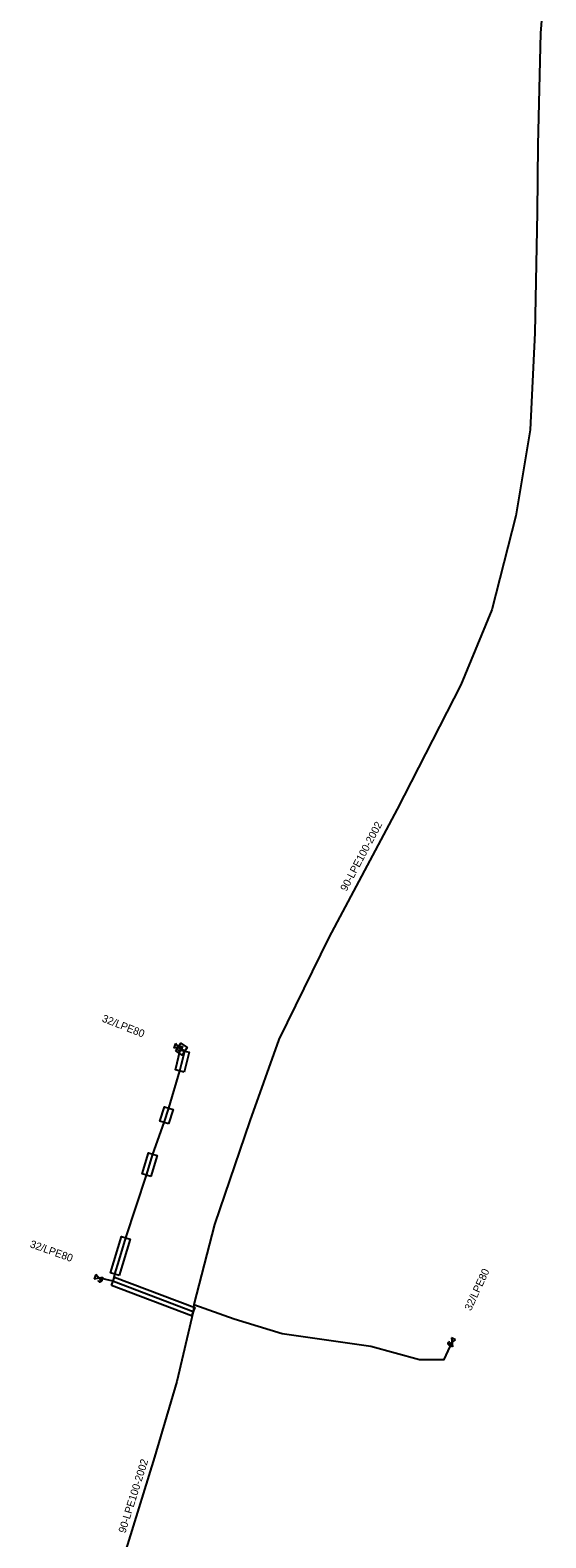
# Model space of a CAD drawing. Extents: x -787723 to -786204, y -1153846 to -1152384.
# Drawn here: x -787402.7 to -787334.7, y -1152971.6 to -1152772.9 of the extents above; entities that cross this region are included whole.
import ezdxf

# ---------------------------------------------------------------- set-up
doc = ezdxf.new("R2010")
doc.units = 0
for name, color, linetype in [('Vrstva 1', 7, 'Continuous'), ('Vrstva 21', 7, 'Continuous'), ('Vrstva 29', 7, 'Continuous'), ('Vrstva 31', 7, 'Continuous'), ('Vrstva 32', 7, 'Continuous')]:
    doc.layers.add(name, color=color, linetype=linetype)

# ---------------------------------------------------------------- blocks, each defined once
blk = doc.blocks.new('DEC063-SN')
at = {"layer": 'Vrstva 1'}
for p, q in [((-0.5, -0.3), (0.5, 0.3)), ((0.5, -0.3), (-0.5, 0.3)), ((-0.5, 0.3), (-0.5, -0.3)), ((0.5, 0.3), (0.5, -0.3)), ((0.126, -0.318), (0.126, -0.458)), ((0.126, -0.384), (0.206, -0.384)), ((0.206, -0.458), (0.206, -0.318)), ((0.366, -0.458), (0.366, -0.318))]:
    blk.add_line(p, q, dxfattribs=at)
for points in [[(0.246, -0.318), (0.246, -0.418), (0.252, -0.438), (0.264, -0.451), (0.281, -0.458), (0.292, -0.458), (0.309, -0.451), (0.321, -0.438), (0.326, -0.418), (0.326, -0.318)], [(0.366, -0.318), (0.418, -0.318), (0.435, -0.325), (0.441, -0.331), (0.446, -0.344), (0.446, -0.364), (0.441, -0.378), (0.435, -0.384), (0.418, -0.391), (0.366, -0.391)]]:
    blk.add_lwpolyline(points, dxfattribs=at)

msp = doc.modelspace()

# ---------------------------------------------------------------- linework, layer by layer
at = {"layer": 'Vrstva 21'}
msp.add_lwpolyline([(-787334.68, -1152764.41), (-787335.37, -1152773.31), (-787335.76, -1152787.99), (-787335.85, -1152796.93), (-787336.15, -1152812.79), (-787336.74, -1152825.56), (-787338.63, -1152836.89), (-787341.8, -1152849.26), (-787345.88, -1152859.17), (-787354.3, -1152875.54), (-787363.3, -1152892.46), (-787369.92, -1152905.89), (-787373.75, -1152916.59), (-787378.4, -1152930.29), (-787381.12, -1152940.81), (-787381.21, -1152941.76), (-787383.36, -1152950.95), (-787386.31, -1152960.92), (-787389.85, -1152972.44), (-787390.54, -1152974.33), (-787393.42, -1152981.16), (-787393.84, -1152982.11), (-787397.85, -1152992.58)], dxfattribs=at)
at = {"layer": 'Vrstva 29'}
for points in [[(-787382.39, -1152910.19), (-787383.55, -1152909.89), (-787382.9, -1152907.29), (-787381.74, -1152907.58)], [(-787383.49, -1152907.39), (-787382.84, -1152906.39), (-787381.99, -1152906.94), (-787382.65, -1152907.94)], [(-787384.46, -1152917.02), (-787385.6, -1152916.66), (-787384.99, -1152914.76), (-787383.85, -1152915.12)], [(-787386.77, -1152923.94), (-787387.93, -1152923.6), (-787387.1, -1152920.82), (-787385.95, -1152921.16)], [(-787390.96, -1152936.97), (-787392.1, -1152936.63), (-787390.66, -1152931.87), (-787389.52, -1152932.21)], [(-787391.99, -1152938.31), (-787391.57, -1152937.19), (-787381, -1152941.2), (-787381.42, -1152942.32)]]:
    msp.add_lwpolyline(points, close=True, dxfattribs=at)
at = {"layer": 'Vrstva 31'}
for points in [[(-787391.78, -1152937.75), (-787391.53, -1152936.8), (-787390.96, -1152934.97), (-787390.09, -1152932.04), (-787387.35, -1152923.77), (-787386.53, -1152920.99), (-787385.03, -1152916.84), (-787384.42, -1152914.94), (-787382.97, -1152910.04), (-787382.73, -1152909.16), (-787382.32, -1152907.44), (-787383.17, -1152906.89)], [(-787391.71, -1152937.78), (-787391.78, -1152937.75), (-787393.69, -1152937.31)], [(-787381.21, -1152941.76), (-787391.71, -1152937.78)], [(-787381.12, -1152940.81), (-787375.81, -1152942.72), (-787369.48, -1152944.64), (-787357.78, -1152946.3), (-787351.33, -1152948.05), (-787348.11, -1152948.06), (-787347.06, -1152945.79)]]:
    msp.add_lwpolyline(points, dxfattribs=at)

# ---------------------------------------------------------------- block references
at = {"layer": 'Vrstva 32'}
for p, rotation in [((-787383.17, -1152906.89), -19.127669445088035), ((-787393.69, -1152937.31), -19.343041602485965), ((-787347.06, -1152945.79), -114.4608333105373)]:
    msp.add_blockref('DEC063-SN', p, dxfattribs=dict(at, rotation=rotation))

# ---------------------------------------------------------------- texts
at = {"layer": 'Vrstva 21'}
for rotation, p in [(61.967, (-787360.98, -1152886.45)), (72.557, (-787390.15, -1152971.01))]:
    msp.add_text('90-LPE100-2002', height=1, rotation=rotation, dxfattribs=at).set_placement(p)
at = {"layer": 'Vrstva 31'}
for rotation, p in [(338.493, (-787393.32, -1152903.5)), (340.323, (-787402.82, -1152933.24)), (65.177, (-787344.56, -1152941.71))]:
    msp.add_text('32/LPE80', height=1, rotation=rotation, dxfattribs=at).set_placement(p)

doc.saveas('drawing.dxf')
